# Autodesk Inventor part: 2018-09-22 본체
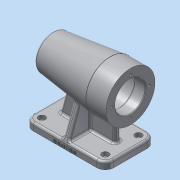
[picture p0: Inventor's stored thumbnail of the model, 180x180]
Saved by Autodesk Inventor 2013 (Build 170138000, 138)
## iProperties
Created: 2018-09
Part Number: 2018-09-22 본체
Material: 알루미늄 6061
Document SubType Name: Modeling
Designer: dgall
Density: 2.71 g/cm^3
Mass: 734.405 g
Surface Area: 664.48 cm^2
Volume: 270.998 cm^3
Author: dgall
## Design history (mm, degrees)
sketch "스케치1"
  geometry: L1 (-56, -35)-(56, -35); L2 (56, -35)-(56, 35); L3 (56, 35)-(-56, 35); L4 (-56, 35)-(-56, -35); L5 (-56, -35)-(56, 35); L6 (56, -35)-(-56, 35); 1 further point
  constraints: 12 end point, 2 midpoint, 2 parallel, 1 horizontal, 1 perpendicular
  dimensions: "d0" = 112 distance of L2.end L3.end; "d2" = 70 distance of L1.end L2.end
extrude "돌출1" new body sketch "스케치1" distance "d3" = 10; taper "d4" = 0 deg
sketch "스케치5"
  geometry: L1 (-56, 74)-(-56, 108); L2 (-56, 108)-(-28, 108); L3 (-28, 108)-(52.27, 98.144); L4 (56, 74)-(-56, 74); L5 (0, 0)-(0, 74); A1 r 80 centre (-24, 74) between (56, 74) and (52.27, 98.144)
  constraints: 10 end point, 2 parallel, 2 point on circle, 1 centre point, 1 midpoint, 1 perpendicular, 1 vertical
  dimensions: "d29" = 112 distance of L4.start L1.start; "d30" = 34 distance of L1.start L1.end; "d31" = 28 distance of L1.end L2.end; "d32" = 7 deg angle of L2 L3; "d33" = 80 radius of A1; "d39" = 74 distance of L5.start L5.end; "d42" = 24.14412 distance from line of L4 L3.end
revolve "회전1" sketch "스케치5" stored, may be unused: angle "d34" = 90 deg
fillet "모깎기1" dims "d35" = 3
fillet "모깎기2" dims "d36" = 3
fillet "모깎기3" dims "d37" = 12
sketch "스케치7"
  geometry: L1 (38, 10)-(21.975, 69.806); L2 (-38, 10)-(-38, 69.806); L3 (-38, 69.806)-(21.975, 69.806); L4 (38, 10)-(-38, 10); L5 (44, 10)-(56, 10) reference; L6 (-56, 10)-(-56, 0) reference; L7 (0, 0)-(0, 10); L8 (-44, 10)-(44, 10) reference
  constraints: 10 end point, 2 midpoint, 1 perpendicular
  dimensions: "d97" = 105 deg angle of L5 L1; "d98" = 76 distance of L1.start L2.start; "d99" = 18 distance from line of L2.start L6; "d100" = 59.80623 distance of L2.start L2.end; "d101" = 59.97497 distance of L2.end L1.end
extrude "돌출5" join sketch "스케치7" stored distance "d51" = 8; taper "d52" = 0 deg
sketch "스케치10"
  geometry: L1 (-4, 10)-(4, 10) reference; L2 (-10.263, 75.216)-(0, 75.216); L3 (0, 75.216)-(0, 10); L4 (-35, 0)-(-35, 10) reference; L5 (23, 0)-(-23, 0) reference; L6 (23, 10)-(-23, 10) reference; L7 (-35, 10)-(-23, 10) reference; L8 (0, 10)-(-34, 10); L9 (-34, 10)-(-10.263, 75.216); 1 further point
  constraints: 8 end point, 3 midpoint, 2 point on line, 1 perpendicular
  dimensions: "d96" = 10.26345 distance of L2.start L2.end; "d107" = 1 distance of L8.end L4.end; "d108" = 70 deg angle of L9 L7
extrude "돌출6" join sketch "스케치10" stored distance "d109" = 8; taper "d110" = 0 deg
node "작업 평면1"
fillet "모깎기6" dims "d112" = 3
fillet "모깎기7" dims "d113" = 3
sketch "스케치11"
  geometry: L1 (0, 0)-(0, 74); L2 (-56, 108)-(-56, 40) reference; L3 (-56, 74)-(50, 74); L4 (43, 90)-(43, 91.5); L5 (43, 91.5)-(25, 91.5); L6 (25, 91.5)-(25, 95); L7 (25, 95)-(13, 95); L8 (13, 95)-(13, 98); L9 (13, 98)-(-41, 98); L10 (-41, 98)-(-41, 95); L11 (-41, 95)-(-56, 95); L12 (43, 90)-(47, 90); L13 (47, 90)-(47, 84.5); L14 (47, 84.5)-(50, 84.5); L15 (50, 84.5)-(50, 74); L16 (-56, 95)-(-56, 74)
  constraints: 30 end point, 4 perpendicular, 2 parallel, 1 collinear, 1 midpoint, 1 point on line, 1 vertical
  dimensions: "d114" = 74 distance of L1.start L1.end; "d115" = 21 distance between parallel lines of L3 L11; "d116" = 15 distance between parallel lines of L10 L2; "d117" = 24 distance between parallel lines of L3 L9; "d118" = 54 distance between parallel lines of L10 L8; "d119" = 21 distance between parallel lines of L3 L7; "d120" = 12 distance from line of L8.end L6; "d121" = 18 distance between parallel lines of L6 L4; "d122" = 17.5 distance between parallel lines of L3 L5; "d123" = 10.5 distance of L14.end L3.end; "d124" = 16 distance between parallel lines of L3 L12; "d125" = 4 distance between parallel lines of L13 L4; "d126" = 3 distance between parallel lines of L15 L13
revolve "회전2" sketch "스케치11" stored, may be unused: angle "d127" = 90 deg
fillet "모깎기8" dims "d128" = 3
fillet "모깎기9" dims "d129" = 3
fillet "모깎기10" dims "d130" = 0.3
fillet "모깎기11" dims "d131" = 0.3
fillet "모깎기12" dims "d132" = 0.3
chamfer "모따기1" distance "d133" = 1; stored, may be unused: second distance "d134" = 2, angle "d135" = 45 deg
sketch "스케치12"
  geometry: C1 r 34 at (0, 0) reference; C2 r 22 at (0, 0) reference; A1 r 26 centre (0, 0) between (-26, 0) and (0, -26); 3 further points
  constraints: 4 point on circle, 2 horizontal alignment, 2 vertical alignment, 1 centre point, 1 coincident
  dimensions: "d136" = 52 diameter of A1
hole "구멍5" sketch "스케치12" at (-26, 0), (0, -26), (26, 0), (0, 26) diameter "d138" = 3.242; stored, may be unused: countersink angle "d142" = 90 deg, drill point angle "d144" = 118 deg; dims "d139" = 8, "d140" = 9.5, "d141" = 5.4, "d143" = 11
hole "구멍6" diameter "d147" = 5.5; stored, may be unused: countersink angle "d151" = 90 deg, drill point angle "d153" = 118 deg; dims "d145" = 10, "d146" = 10, "d148" = 8, "d149" = 9.5, "d150" = 5.4, "d152" = 11
hole "구멍7" diameter "d156" = 5.5; stored, may be unused: countersink angle "d160" = 90 deg, drill point angle "d162" = 118 deg; dims "d154" = 10, "d155" = 10, "d157" = 8, "d158" = 9.5, "d159" = 5.4, "d161" = 11
hole "구멍8" diameter "d165" = 5.5; stored, may be unused: countersink angle "d169" = 90 deg, drill point angle "d171" = 118 deg; dims "d163" = 10, "d164" = 10, "d166" = 8, "d167" = 9.5, "d168" = 5.4, "d170" = 11
hole "구멍9" diameter "d174" = 5.5; stored, may be unused: countersink angle "d178" = 90 deg, drill point angle "d180" = 118 deg; dims "d172" = 10, "d173" = 10, "d175" = 8, "d176" = 9.5, "d177" = 5.4, "d179" = 11
sketch "스케치13"
  geometry: L1 (100, 0)-(100, 7) reference; 2 further points
  constraints: 1 other
  dimensions: "d181" = 3 distance of point (44, 0) point (44, 3); "d182" = 56 distance from line of L1 point (44, 3)
feature "엠보싱1" sketch "스케치13" dims "d0" = 112, "d2" = 70, "d183" = 0.5, "d184" = 0
fillet "모깎기13" dims "d185" = 3
node "솔리드1"
mirror "대칭1"
other parameters: "d5" = 8, "d7" = 8, "d111" = 0
